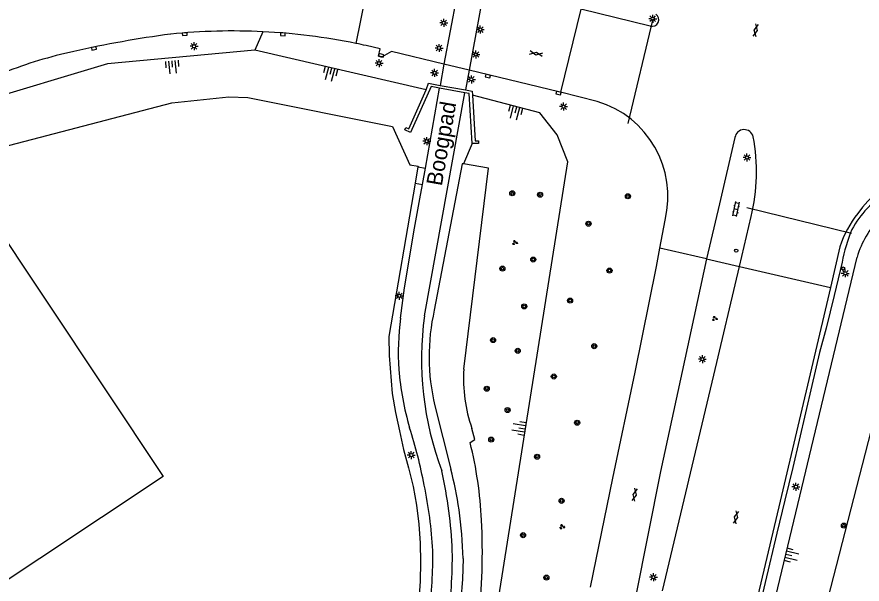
# Model space of a CAD drawing. Extents: x 131000 to 133013, y 393000 to 396501.
# Drawn here: x 131304.2 to 131437.5, y 394306.4 to 394396 of the extents above; entities that cross this region are included whole.
import ezdxf

# ---------------------------------------------------------------- set-up
doc = ezdxf.new("R2010")
doc.units = 0
for name, color, linetype in [('gg-afsc-hekwerk', 7, 'Continuous'), ('gg-anno-openbare ruimte label', 7, 'Continuous'), ('gg-bbg-hoofdgebouw', 7, 'Continuous'), ('gg-knt-BGT kruinlijn', 7, 'Continuous'), ('gg-knt-bovenkant onderkant talud', 7, 'Continuous'), ('gg-knt-verharding', 7, 'Continuous'), ('gg-knt-verharding niveau 01', 7, 'Continuous'), ('gg-kntw-bovenkant insteek waterloop', 7, 'Continuous'), ('gg-kwrk-kunstwerk', 7, 'Continuous'), ('gg-kwrk-kunstwerk niveau 01', 7, 'Continuous'), ('gt-grn-groengrens', 7, 'Continuous'), ('gt-grn-weggrens', 7, 'Continuous'), ('gt-knt-geleideconstructie', 7, 'Continuous'), ('gt-knt-lijn portaal', 7, 'Continuous'), ('gt-symb-boom', 7, 'Continuous'), ('gt-symb-gesloten verharding', 7, 'Continuous'), ('gt-symb-groenvak', 7, 'Continuous'), ('gt-symb-klinker verharding', 7, 'Continuous'), ('gt-symb-kolk', 7, 'Continuous'), ('gt-symb-lichtmast', 7, 'Continuous'), ('gt-symb-talud symbool', 7, 'Continuous'), ('gt-symb-verkeersregelinstallatiepaal', 7, 'Continuous')]:
    doc.layers.add(name, color=color, linetype=linetype)

# ---------------------------------------------------------------- blocks, each defined once
blk = doc.blocks.new('gt0-LMAST')
at = {"layer": 'gt-symb-lichtmast'}
for p, q in [((-0.18, 0.17), (-0.45, 0.44)), ((-0.01, 0.25), (-0.01, 0.62)), ((0.17, 0.17), (0.44, 0.44)), ((-0.26, 0), (-0.63, 0)), ((-0.18, -0.18), (-0.45, -0.45)), ((-0.01, -0.25), (-0.01, -0.63)), ((0.44, -0.45), (0.17, -0.18)), ((0.24, 0), (0.62, 0))]:
    blk.add_line(p, q, dxfattribs=at)
blk.add_circle((-0.01, 0), 0.25, dxfattribs=at)
blk = doc.blocks.new('gt0-GESVH1')
at = {"layer": 'gt-symb-gesloten verharding'}
for p, q in [((-0.99, -0.26), (0.01, 0.24)), ((0.01, -0.26), (-0.99, 0.24)), ((0.01, 0.24), (1.01, -0.26)), ((1.01, 0.24), (0.01, -0.26))]:
    blk.add_line(p, q, dxfattribs=at)
blk = doc.blocks.new('gt0-TALUD_1')
at = {"layer": 'gt-symb-talud symbool'}
for p, q in [((-1, -1), (-1, 0)), ((-0.5, -2), (-0.5, 0)), ((0, -1), (0, 0)), ((0.5, -2), (0.5, 0)), ((1, -1), (1, 0))]:
    blk.add_line(p, q, dxfattribs=at)
blk = doc.blocks.new('gt0-KOLK')
at = {"layer": 'gt-symb-kolk'}
blk.add_lwpolyline([(0, 0), (0.37, 0), (0.37, 0.4), (-0.38, 0.4), (-0.38, 0), (0, 0)], dxfattribs=at)
blk = doc.blocks.new('gt0-BOOM')
at = {"layer": 'gt-symb-boom'}
for radius in [0.4, 0.2]:
    blk.add_circle((0, 0), radius, dxfattribs=at)
blk = doc.blocks.new('gt0-GRVAK')
at = {"layer": 'gt-symb-groenvak'}
for p, q in [((-0.11, 0.19), (-0.23, 0.24)), ((-0.18, 0.15), (0.09, 0.15)), ((-0.09, 0.21), (-0.16, 0.32)), ((-0.05, 0.21), (-0.05, 0.39)), ((0, 0.21), (0.06, 0.32)), ((0.02, 0.19), (0.13, 0.24)), ((0.26, -0.05), (0.2, 0.06)), ((0.31, -0.05), (0.31, 0.13)), ((0.35, -0.05), (0.41, 0.06)), ((-0.24, -0.23), (-0.36, -0.18)), ((-0.32, -0.26), (-0.05, -0.26)), ((-0.23, -0.21), (-0.29, -0.09)), ((-0.18, -0.2), (-0.18, -0.02)), ((-0.14, -0.21), (-0.07, -0.09)), ((-0.12, -0.23), (0, -0.18)), ((0.24, -0.07), (0.12, -0.02)), ((0.17, -0.11), (0.44, -0.11)), ((0.37, -0.07), (0.49, -0.02))]:
    blk.add_line(p, q, dxfattribs=at)
blk = doc.blocks.new('gt0-VIPAAL')
at = {"layer": 'gt-symb-verkeersregelinstallatiepaal'}
blk.add_circle((0, 0), 0.25, dxfattribs=at)
blk = doc.blocks.new('gt0-KL1')
at = {"layer": 'gt-symb-klinker verharding'}
for p, q in [((-1.15, 0.3), (1.15, 0.3)), ((-1, -0.3), (-1, 0.3)), ((-0.5, 0.3), (-0.5, 0.45)), ((0, -0.3), (0, 0.3)), ((0.5, 0.3), (0.5, 0.45)), ((1, -0.3), (1, 0.3)), ((-1.15, -0.3), (1.15, -0.3)), ((-0.5, -0.45), (-0.5, -0.3)), ((0.5, -0.45), (0.5, -0.3))]:
    blk.add_line(p, q, dxfattribs=at)

msp = doc.modelspace()

# ---------------------------------------------------------------- linework, layer by layer
at = {"layer": 'gg-afsc-hekwerk'}
msp.add_line((131367.4, 394372.35), (131366.99, 394369.76), dxfattribs=at)
for points in [[(131298.38, 394374.55), (131328.6, 394382.44), (131337.57, 394383.38), (131340.58, 394383.3), (131363.43, 394378.69), (131366.16, 394372.63), (131367.44, 394372.44), (131367.4, 394372.35)], [(131366.99, 394369.76), (131362.83, 394345.53), (131362.91, 394342.51), (131363.38, 394336.52), (131363.9, 394333.55), (131364.5, 394330.61), (131365.17, 394327.68), (131365.94, 394324.77), (131366.68, 394321.85), (131367.19, 394318.88), (131367.55, 394315.9), (131367.8, 394312.9), (131367.81, 394309.89), (131367.78, 394306.88), (131367.35, 394300.89), (131363.84, 394283.2)]]:
    msp.add_lwpolyline(points, dxfattribs=at)
at = {"layer": 'gg-bbg-hoofdgebouw'}
msp.add_lwpolyline([(131182.54, 394287.65), (131299.35, 394365.3), (131327.21, 394323.4), (131210.4, 394245.73)], dxfattribs=at)
at = {"layer": 'gg-knt-BGT kruinlijn'}
msp.add_line((131368.75, 394384.51), (131341.7, 394390.75), dxfattribs=at)
for points in [[(131341.7, 394390.75), (131318.45, 394388.59), (131297.71, 394382.4)], [(131381.66, 394282.36), (131384.61, 394296.52), (131379.12, 394297.79), (131391.06, 394373.14), (131389.4, 394377.36), (131386.64, 394380.87), (131376.06, 394383.67)], [(131409.62, 394245.17), (131409.85, 394245.94), (131436.72, 394358.07)]]:
    msp.add_lwpolyline(points, dxfattribs=at)
for centre, radius, start, end in [((131342.08, 394312.23), 104.22, 106.1519, 128.9476), ((131450.96, 394353.91), 14.83, 135.5912, 163.7139)]:
    msp.add_arc(centre, radius, start, end, dxfattribs=at)
at = {"layer": 'gg-knt-bovenkant onderkant talud'}
msp.add_lwpolyline([(131414.92, 394242.7), (131427.12, 394284.56), (131443.52, 394348.38)], dxfattribs=at)
at = {"layer": 'gg-knt-verharding'}
for p, q in [((131404.09, 394394.57), (131393.12, 394397.25)), ((131371.54, 394388.55), (131363.24, 394390.57)), ((131368.6, 394372.14), (131370.84, 394384.77)), ((131368.45, 394348.82), (131374.84, 394384.04)), ((131395.71, 394382.66), (131389.91, 394384.1)), ((131367.4, 394372.35), (131368.6, 394372.14)), ((131368.14, 394369.56), (131368.6, 394372.14)), ((131366.99, 394369.76), (131368.14, 394369.56)), ((131405.61, 394359.48), (131406.42, 394363.91)), ((131418.14, 394356.57), (131420.01, 394364.47)), ((131434.02, 394359.71), (131432.5, 394353.26)), ((131412.98, 394357.78), (131418.14, 394356.57))]:
    msp.add_line(p, q, dxfattribs=at)
for points in [[(131363.24, 394390.57), (131361.78, 394389.68), (131361.2, 394389.82), (131361.45, 394390.97), (131359.27, 394391.47)], [(131389.91, 394384.1), (131389.66, 394384.16), (131375.49, 394387.59)], [(131417.44, 394376.98), (131415, 394366.51), (131412.98, 394357.78)], [(131364.67, 394348.45), (131365.29, 394353.23), (131366.87, 394362.66), (131367.74, 394367.3), (131368.14, 394369.56)], [(131394.67, 394305.96), (131398.16, 394323.16), (131401.69, 394339.9), (131405.07, 394356.57), (131405.61, 394359.48)], [(131412.98, 394357.78), (131409.52, 394341.96), (131405.68, 394324.21), (131401.73, 394304.35)], [(131406, 394305.38), (131414.11, 394339.44), (131418.14, 394356.57)], [(131432.5, 394353.26), (131424.59, 394319.54), (131420.09, 394300.62), (131415.81, 394282.82), (131411.48, 394265.01), (131406.85, 394246.47)]]:
    msp.add_lwpolyline(points, dxfattribs=at)
for centre, radius, start, end in [((131342.51, 394314.14), 99.79, 106.6061, 129.6166), ((131404.38, 394395.58), 1.05, 253.9089, 56.5446), ((131352.18, 394216.1), 178.78, 97.6394, 102.6165), ((131338.22, 394297.16), 96.63, 87.1795, 95.8198), ((131338.22, 394297.02), 96.77, 78.4376, 87.1862), ((131338.21, 394296.98), 96.81, 77.4325, 78.4347), ((131328.5, 394320.25), 71.97, 102.3312, 111.4602), ((131391.25, 394367.68), 15.63, 346.053, 73.4143), ((131418.9, 394376.73), 1.48, 14.3051, 170.292), ((131390.79, 394371.53), 30.06, 346.4088, 10.6704), ((131450.4, 394355.53), 16.53, 76.6675, 145.1656), ((131449.4, 394354.85), 16.13, 141.1593, 162.4605), ((131418.85, 394342.02), 50.85, 172.3154, 200.3984), ((131410, 394342.83), 45.68, 172.9358, 183.1435), ((131410.53, 394344.16), 46.29, 184.7527, 196.3679), ((131294.76, 394308.16), 74.95, 10.6792, 17.8331), ((131304.35, 394309.08), 68.55, 2.1661, 12.8282), ((131300.39, 394307.91), 69.48, 3.1609, 11.7414), ((131306.56, 394310.46), 63.21, 352.0396, 1.1659), ((131303.64, 394310.7), 69.22, 351.4521, 0.807)]:
    msp.add_arc(centre, radius, start, end, dxfattribs=at)
at = {"layer": 'gg-knt-verharding niveau 01'}
msp.add_line((131375.49, 394387.59), (131371.54, 394388.55), dxfattribs=at)
at = {"layer": 'gg-kntw-bovenkant insteek waterloop'}
msp.add_line((131370.09, 394334.6), (131372.6, 394324.59), dxfattribs=at)
for points in [[(131374.63, 394372.79), (131374.43, 394372.82), (131370, 394349.71)], [(131374.68, 394340.38), (131378.56, 394372.11), (131374.63, 394372.79)], [(131375.66, 394328.78), (131376.41, 394329.28), (131375.94, 394331.02)], [(131374.55, 394310.46), (131374.46, 394307.2), (131374.2, 394303.96), (131373.88, 394300.99), (131373.44, 394298.04), (131369.4, 394277.11)]]:
    msp.add_lwpolyline(points, dxfattribs=at)
for centre, radius, start, end in [((131403.03, 394342.34), 33.84, 167.4336, 193.2338), ((131398.05, 394338.78), 23.43, 176.0854, 199.3285), ((131313.63, 394313.42), 63.91, 2.7753, 13.9059), ((131324.23, 394311.32), 50.16, 7.8465, 15.3422), ((131308.2, 394308.94), 66.36, 1.3061, 7.99), ((131273.57, 394311.32), 104.02, 354.0598, 2.86)]:
    msp.add_arc(centre, radius, start, end, dxfattribs=at)
at = {"layer": 'gg-kwrk-kunstwerk'}
for p, q in [((131374.84, 394384.04), (131370.84, 394384.77)), ((131366.28, 394377.75), (131365.36, 394378.17))]:
    msp.add_line(p, q, dxfattribs=at)
for points in [[(131370.84, 394384.77), (131369.5, 394385.01), (131366.28, 394377.75)], [(131368.75, 394384.51), (131369.11, 394385.53), (131370.92, 394385.2)], [(131365.36, 394378.17), (131365.52, 394378.54), (131366, 394378.33), (131368.75, 394384.51)], [(131375.99, 394376), (131375.49, 394383.92), (131374.84, 394384.04)], [(131374.92, 394384.48), (131376, 394384.29), (131376.06, 394383.67)], [(131376.06, 394383.67), (131376.45, 394376.43), (131376.99, 394376.42), (131377.01, 394376.04), (131375.99, 394376)]]:
    msp.add_lwpolyline(points, dxfattribs=at)
at = {"layer": 'gg-kwrk-kunstwerk niveau 01'}
for p, q in [((131374.03, 394401.92), (131371.54, 394388.55)), ((131377.94, 394400.97), (131375.49, 394387.59)), ((131371.54, 394388.55), (131370.92, 394385.2)), ((131375.49, 394387.59), (131374.92, 394384.48)), ((131370.92, 394385.2), (131374.92, 394384.48))]:
    msp.add_line(p, q, dxfattribs=at)
at = {"layer": 'gt-grn-groengrens'}
for p, q in [((131342.97, 394393.67), (131341.7, 394390.75)), ((131375.99, 394376), (131374.63, 394372.79))]:
    msp.add_line(p, q, dxfattribs=at)
at = {"layer": 'gt-grn-weggrens'}
for p, q in [((131360.36, 394405.26), (131357.62, 394391.82)), ((131393.12, 394397.25), (131389.91, 394384.1)), ((131412.98, 394357.78), (131405.61, 394359.48)), ((131418.14, 394356.57), (131432.5, 394353.26))]:
    msp.add_line(p, q, dxfattribs=at)
at = {"layer": 'gt-knt-geleideconstructie'}
msp.add_lwpolyline([(131434.36, 394357.26), (131433.1, 394352.03), (131431.86, 394346.85), (131430.81, 394343), (131429.6, 394337.81), (131426.56, 394324.85), (131425.32, 394319.66), (131424.08, 394314.45), (131420.35, 394298.9)], dxfattribs=at)
for centre, radius, start, end in [((131449.3, 394355.23), 15.21, 120.8409, 151.8031), ((131459.01, 394352.74), 25.06, 157.2994, 169.6284)]:
    msp.add_arc(centre, radius, start, end, dxfattribs=at)
at = {"layer": 'gt-knt-lijn portaal'}
for p, q in [((131404.49, 394395.72), (131400.54, 394379.18)), ((131419.34, 394365.9), (131435.85, 394361.85))]:
    msp.add_line(p, q, dxfattribs=at)

# ---------------------------------------------------------------- block references
at = {"layer": 'gt-symb-boom'}
for p in [(131382.32, 394368.16), (131386.69, 394367.92), (131400.56, 394367.69), (131394.34, 394363.35), (131385.62, 394357.69), (131380.76, 394356.26), (131397.65, 394355.95), (131391.44, 394351.21), (131384.2, 394350.28), (131379.29, 394344.96), (131383.17, 394343.27), (131395.25, 394344.01), (131388.87, 394339.22), (131378.29, 394337.28), (131381.58, 394333.91), (131392.55, 394331.91), (131379, 394329.24), (131386.23, 394326.55), (131390.09, 394319.58), (131434.64, 394315.67), (131384.01, 394314.16), (131387.7, 394307.45)]:
    msp.add_blockref('gt0-BOOM', p, dxfattribs=at)
at = {"layer": 'gt-symb-gesloten verharding'}
for p, rotation in [((131420.74, 394393.9), -101.24252570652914), ((131386.06, 394390.23), -9.321060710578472), ((131401.63, 394320.55), -101.82670392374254), ((131417.63, 394316.99), -101.82670392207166)]:
    msp.add_blockref('gt0-GESVH1', p, dxfattribs=dict(at, rotation=rotation))
at = {"layer": 'gt-symb-groenvak'}
for p in [(131382.73, 394360.36), (131414.24, 394348.37), (131390.17, 394315.49)]:
    msp.add_blockref('gt0-GRVAK', p, dxfattribs=at)
at = {"layer": 'gt-symb-klinker verharding', "rotation": -101.24252570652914}
msp.add_blockref('gt0-KL1', (131417.59, 394365.67), dxfattribs=at)
at = {"layer": 'gt-symb-kolk'}
for p, rotation in [((131330.62, 394393.49), -176.56814187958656), ((131346.12, 394393.47), 175.58148924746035), ((131316.28, 394391.23), -168.24849944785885), ((131361.57, 394389.73), -13.570434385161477), ((131378.5, 394386.86), 166.4119823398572), ((131389.66, 394384.16), 166.07924048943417)]:
    msp.add_blockref('gt0-KOLK', p, dxfattribs=dict(at, rotation=rotation))
at = {"layer": 'gt-symb-lichtmast'}
for p in [(131371.5, 394395.08), (131404.49, 394395.72), (131377.28, 394394.02), (131332.11, 394391.38), (131370.77, 394391.1), (131376.58, 394390.08), (131361.3, 394388.71), (131370.06, 394387.18), (131375.87, 394386.14), (131390.41, 394381.85), (131368.83, 394376.38), (131419.35, 394373.81), (131434.86, 394355.51), (131364.49, 394351.96), (131412.31, 394341.96), (131366.38, 394326.8), (131427.07, 394321.8), (131404.58, 394307.52)]:
    msp.add_blockref('gt0-LMAST', p, dxfattribs=at)
at = {"layer": 'gt-symb-talud symbool'}
for p, xscale, yscale, rotation in [((131328.63, 394389.06), 1.0003324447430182, 1.0003324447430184, 5.334440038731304), ((131353.83, 394387.95), 1.0003124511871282, 1.000312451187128, -14.828108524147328), ((131383.01, 394381.83), 1.0003124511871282, 1.000312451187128, -14.828108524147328), ((131384.32, 394330.96), 0.9997329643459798, 0.9997329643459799, -99.84862238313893), ((131425.45, 394311.12), 0.9995363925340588, 0.9995363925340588, 76.51987378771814)]:
    msp.add_blockref('gt0-TALUD_1', p, dxfattribs=dict(at, xscale=xscale, yscale=yscale, rotation=rotation))
at = {"layer": 'gt-symb-verkeersregelinstallatiepaal', "rotation": -102.97344743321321}
for p in [(131417.65, 394359.1), (131434.52, 394356.27)]:
    msp.add_blockref('gt0-VIPAAL', p, dxfattribs=at)

# ---------------------------------------------------------------- texts
at = {"layer": 'gg-anno-openbare ruimte label'}
msp.add_text('Boogpad', height=2.5, rotation=80.1, dxfattribs=at).set_placement((131371.19, 394369.21))

doc.saveas('drawing.dxf')
